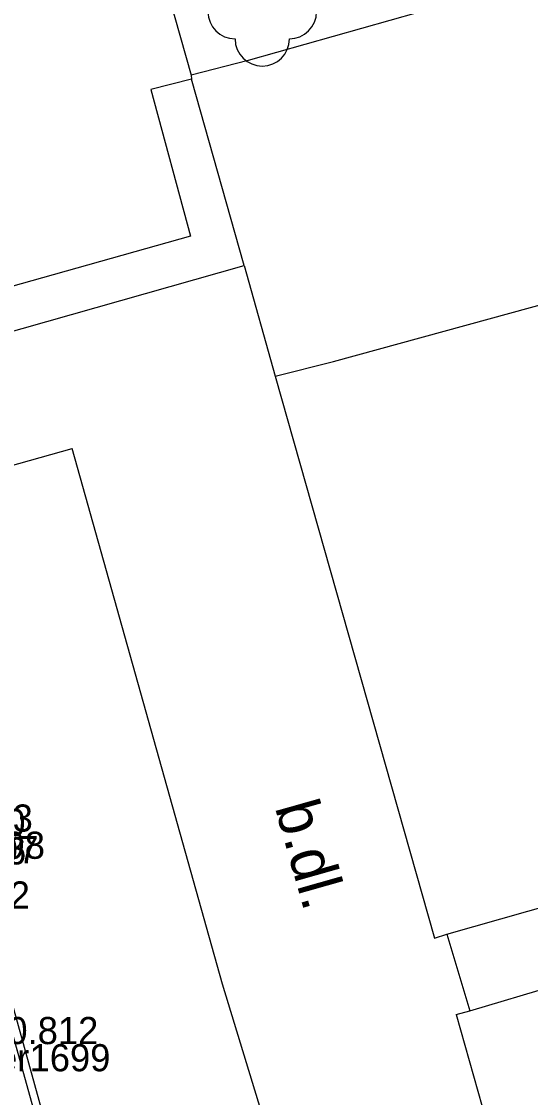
# Model space of a CAD drawing. Extents: x -599098 to -598820, y -1159597 to -1158744.
# Drawn here: x -599005 to -598995.63, y -1158933.02 to -1158913.22 of the extents above; entities that cross this region are included whole.
import ezdxf

# ---------------------------------------------------------------- set-up
doc = ezdxf.new("R2010")
doc.units = 0
for name, color, linetype in [('body', 7, 'Continuous'), ('druh pozemku stromy', 7, 'Continuous'), ('kresba', 7, 'Continuous'), ('kódy bodů', 7, 'Continuous'), ('popisy', 7, 'Continuous'), ('výšky bodů', 7, 'Continuous'), ('čísla bodů', 7, 'Continuous')]:
    doc.layers.add(name, color=color, linetype=linetype)

msp = doc.modelspace()

# ---------------------------------------------------------------- linework, layer by layer
at = {"layer": 'body'}
msp.add_line((-599004.852, -1158932.043), (-599004.852, -1158932.043), dxfattribs=at)
at = {"layer": 'druh pozemku stromy'}
for centre, start, end in [((-599001.07, -1158913.04), 90, 270), ((-599000.07, -1158913.04), 270, 90), ((-599000.57, -1158913.54), 180, 360)]:
    msp.add_arc(centre, 0.5, start, end, dxfattribs=at)
at = {"layer": 'kresba'}
for p, q in [((-599003.406, -1158908.738), (-599001.88, -1158914.21)), ((-598997.18, -1158912.91), (-599000.83, -1158913.94)), ((-599000.83, -1158913.94), (-599001.88, -1158914.21)), ((-599001.87, -1158914.28), (-599002.62, -1158914.47)), ((-599001.88, -1158914.21), (-599001.87, -1158914.28)), ((-599000.9, -1158917.71), (-599001.87, -1158914.28)), ((-599002.62, -1158914.47), (-599001.89, -1158917.17)), ((-599001.89, -1158917.17), (-599007.82, -1158918.84)), ((-598999.26, -1158919.48), (-598992.2, -1158917.54)), ((-599007.6, -1158919.61), (-599000.9, -1158917.71)), ((-599000.9, -1158917.71), (-599000.33, -1158919.75)), ((-599000.33, -1158919.75), (-598999.26, -1158919.48)), ((-599000.33, -1158919.75), (-598997.4, -1158930.09)), ((-599007.727, -1158922.1), (-599004.069, -1158921.081)), ((-599001.3, -1158930.94), (-599004.069, -1158921.081)), ((-599003.5, -1158937.84), (-599006.177, -1158928.215)), ((-599006.057, -1158928.132), (-599003.36, -1158937.811)), ((-598997.17, -1158930.02), (-598993.91, -1158929.09)), ((-598997.4, -1158930.09), (-598997.17, -1158930.02)), ((-598997.17, -1158930.02), (-598996.75, -1158931.43)), ((-598996.75, -1158931.43), (-598993.33, -1158930.41)), ((-598998.94, -1158938.71), (-599001.3, -1158930.94)), ((-598997, -1158931.5), (-598996.75, -1158931.43)), ((-598997, -1158931.5), (-598992.34, -1158947.96))]:
    msp.add_line(p, q, dxfattribs=at)

# ---------------------------------------------------------------- texts
at = {"layer": 'kódy bodů'}
msp.add_text('ker', height=0.5, dxfattribs=at).set_placement((-599005.785, -1158932.543))
at = {"layer": 'popisy'}
msp.add_text('b.dl.', height=0.8, rotation=285.8209, dxfattribs=at).set_placement((-599000.341, -1158927.681))
at = {"layer": 'výšky bodů'}
for s, p in [('240.783', (-599007.209, -1158928.132)), ('240.630', (-599007.343, -1158928.215)), ('240.812', (-599006.004, -1158932.043))]:
    msp.add_text(s, height=0.5, dxfattribs=at).set_placement(p)
at = {"layer": 'čísla bodů'}
for s, p in [('1696', (-599006.402, -1158928.736)), ('1697', (-599006.177, -1158928.715)), ('1698', (-599006.057, -1158928.632)), ('1692', (-599006.333, -1158929.548)), ('1699', (-599004.852, -1158932.543))]:
    msp.add_text(s, height=0.5, dxfattribs=at).set_placement(p)

doc.saveas('drawing.dxf')
